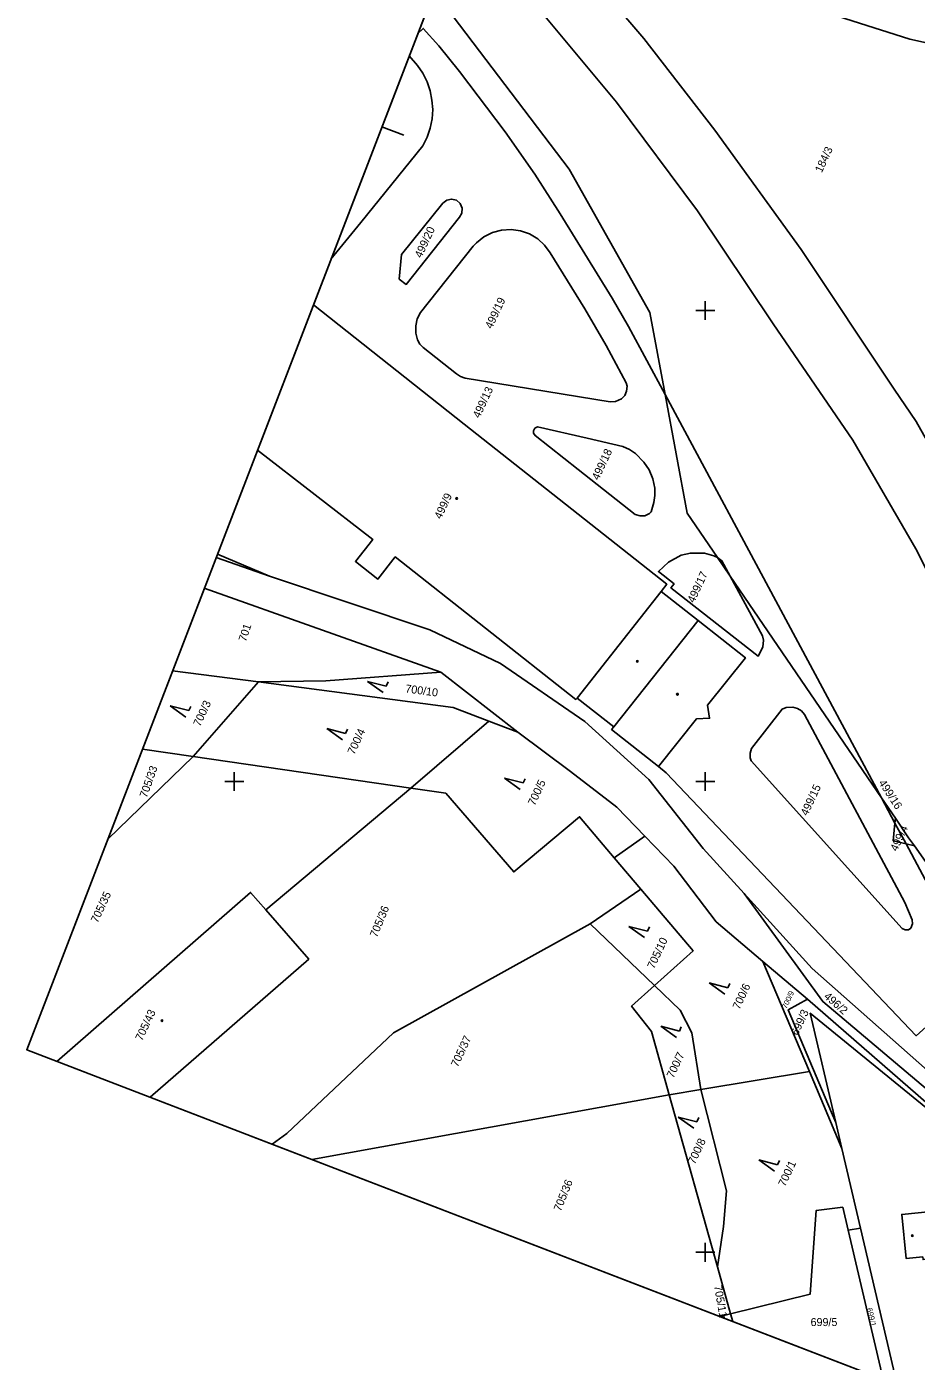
# Model space of a CAD drawing. Extents: x -755344 to -754413, y -1162670 to -1161477.
# Drawn here: x -755344.1 to -755155.2, y -1162523.1 to -1162239.7 of the extents above; entities that cross this region are included whole.
import ezdxf

# ---------------------------------------------------------------- set-up
doc = ezdxf.new("R2010")
doc.units = 0
for name, color, linetype in [('Formát', 7, 'Continuous'), ('Síť', 7, 'Continuous'), ('Vrstva 55', 7, 'Continuous'), ('Vrstva 56', 7, 'Continuous'), ('Vrstva 57', 7, 'Continuous'), ('Vrstva 58', 7, 'Continuous'), ('Vrstva 59', 7, 'Continuous')]:
    doc.layers.add(name, color=color, linetype=linetype)

msp = doc.modelspace()

# ---------------------------------------------------------------- linework, layer by layer
at = {"layer": 'Formát'}
for p, q in [((-755042.37, -1161673.02), (-755344.08, -1162456.97)), ((-755042.37, -1161673.02), (-755344.08, -1162456.97)), ((-755268.65, -1162260.99), (-755263.98, -1162262.78)), ((-755344.08, -1162456.97), (-754789.71, -1162670.32))]:
    msp.add_line(p, q, dxfattribs=at)
msp.add_lwpolyline([(-754488.01, -1161886.37), (-754789.71, -1162670.32), (-755344.08, -1162456.97), (-755042.37, -1161673.02)], close=True, dxfattribs=at)
for points in [[(-755344.08, -1162456.97), (-754789.71, -1162670.32), (-754488.01, -1161886.37), (-755042.37, -1161673.02)], [(-755344.08, -1162456.97), (-754789.71, -1162670.32), (-754488.01, -1161886.37), (-755042.37, -1161673.02)], [(-754789.71, -1162670.32), (-754488.01, -1161886.37), (-755042.37, -1161673.02), (-755344.08, -1162456.97)]]:
    msp.add_lwpolyline(points, dxfattribs=at)
at = {"layer": 'Síť'}
for points in [[(-755198, -1162300), (-755200, -1162300), (-755202, -1162300)], [(-755200, -1162298), (-755200, -1162300), (-755200, -1162302)], [(-755300, -1162398), (-755300, -1162400), (-755300, -1162402)], [(-755200, -1162398), (-755200, -1162400), (-755200, -1162402)], [(-755298, -1162400), (-755300, -1162400), (-755302, -1162400)], [(-755198, -1162400), (-755200, -1162400), (-755202, -1162400)], [(-755200, -1162498), (-755200, -1162500), (-755200, -1162502)], [(-755198, -1162500), (-755200, -1162500), (-755202, -1162500)]]:
    msp.add_lwpolyline(points, dxfattribs=at)
at = {"layer": 'Vrstva 55'}
for p, q in [((-755197.4, -1162352.43), (-755194.7, -1162356.4)), ((-755194.7, -1162356.4), (-755162.59, -1162403.5)), ((-755256.17, -1162376.79), (-755306.36, -1162358.97)), ((-755256.17, -1162376.79), (-755306.36, -1162358.97)), ((-755256.17, -1162376.79), (-755280.56, -1162378.65)), ((-755239.79, -1162389.54), (-755256.17, -1162376.79)), ((-755239.79, -1162389.54), (-755256.17, -1162376.79)), ((-755308.72, -1162394.69), (-755294.89, -1162378.88)), ((-755280.56, -1162378.65), (-755294.89, -1162378.88)), ((-755262.5, -1162401.42), (-755245.93, -1162387.2)), ((-755239.79, -1162389.54), (-755245.93, -1162387.2)), ((-755228.6, -1162397.87), (-755239.79, -1162389.54)), ((-755228.6, -1162397.87), (-755239.79, -1162389.54)), ((-755319.5, -1162393.12), (-755308.72, -1162394.69)), ((-755326.86, -1162412.25), (-755308.72, -1162394.69)), ((-755308.72, -1162394.69), (-755262.5, -1162401.42)), ((-755293.31, -1162427.26), (-755262.5, -1162401.42)), ((-755262.5, -1162401.42), (-755255.05, -1162402.51)), ((-755162.59, -1162403.5), (-755159.64, -1162407.83)), ((-755159.74, -1162408.83), (-755162.59, -1162403.5)), ((-755159.64, -1162407.83), (-755159.74, -1162408.83)), ((-755219.35, -1162416.19), (-755212.85, -1162411.61)), ((-755157.36, -1162413.27), (-755155.59, -1162413.71)), ((-755219.35, -1162416.19), (-755213.66, -1162422.91)), ((-755213.66, -1162422.91), (-755224.46, -1162430.27)), ((-755224.46, -1162430.27), (-755210.79, -1162443.34)), ((-755178.31, -1162446.22), (-755187.75, -1162438.21)), ((-755177.87, -1162461.62), (-755187.75, -1162438.21)), ((-755178.31, -1162446.22), (-755187.75, -1162438.21)), ((-755136.42, -1162482.75), (-755178.31, -1162446.22)), ((-755136.42, -1162482.75), (-755178.31, -1162446.22)), ((-755211.4, -1162453.1), (-755207.64, -1162466.53)), ((-755177.87, -1162461.62), (-755200.95, -1162465.43)), ((-755170.99, -1162477.93), (-755177.87, -1162461.62)), ((-755207.64, -1162466.53), (-755283.5, -1162480.29)), ((-755207.64, -1162466.53), (-755200.95, -1162465.43)), ((-755207.64, -1162466.53), (-755197.41, -1162503.06)), ((-755172.28, -1162472.41), (-755170.99, -1162477.93)), ((-755170.99, -1162477.93), (-755167.04, -1162494.84)), ((-755169.63, -1162495.32), (-755170.76, -1162490.41)), ((-755167.04, -1162494.84), (-755169.63, -1162495.32)), ((-755169.63, -1162495.32), (-755162.24, -1162526.95)), ((-755197.41, -1162503.06), (-755194.62, -1162513.04)), ((-755196.07, -1162513.44), (-755196.82, -1162513.65)), ((-755194.62, -1162513.04), (-755196.07, -1162513.44)), ((-755194.16, -1162514.67), (-755194.62, -1162513.04))]:
    msp.add_line(p, q, dxfattribs=at)
for points in [[(-755251.78, -1162217.14), (-755236.92, -1162234.12), (-755218.86, -1162255.78), (-755201.65, -1162278.82), (-755185.6, -1162302.84), (-755168.69, -1162327.53), (-755155.26, -1162350.62), (-755154.66, -1162351.82), (-755141.68, -1162377.77), (-755128.84, -1162403.34)], [(-755224.59, -1162220.51), (-755227.6, -1162225.16), (-755213.03, -1162242.21), (-755197.95, -1162261.69), (-755179.66, -1162287.01), (-755159.89, -1162316.68), (-755155.21, -1162323.55), (-755152.98, -1162327.62)], [(-755140.31, -1162246.01), (-755156.59, -1162242.36), (-755179.53, -1162235.08), (-755202.91, -1162226.05)], [(-755257.56, -1162232.16), (-755228.92, -1162270), (-755211.8, -1162300.42), (-755208.54, -1162317.82)], [(-755261.01, -1162241.13), (-755259.86, -1162240.09), (-755256.55, -1162243.81), (-755252.15, -1162249.27), (-755242.47, -1162262.02), (-755236.16, -1162271.02), (-755230.79, -1162279.46), (-755219.8, -1162297.35), (-755216.28, -1162303.42), (-755208.54, -1162317.82)], [(-755279.48, -1162289.12), (-755273.15, -1162281.3), (-755259.96, -1162264.99), (-755259.05, -1162263.18), (-755258.42, -1162261.28), (-755258.01, -1162259.3), (-755257.86, -1162257.3), (-755258.04, -1162255.29), (-755258.42, -1162253.32), (-755259.06, -1162251.4), (-755259.94, -1162249.61), (-755261.07, -1162247.95), (-755262.85, -1162245.91)], [(-755264.53, -1162288.11), (-755255.71, -1162277.19), (-755254.89, -1162276.55), (-755253.87, -1162276.34), (-755252.85, -1162276.59), (-755252.05, -1162277.27), (-755251.62, -1162278.23), (-755251.7, -1162279.29), (-755252.21, -1162280.19), (-755263.5, -1162294.45), (-755265.01, -1162293.32), (-755264.53, -1162288.11)], [(-755249.26, -1162286.35), (-755248.56, -1162285.61), (-755246.99, -1162284.35), (-755245.19, -1162283.44), (-755243.24, -1162282.9), (-755241.22, -1162282.77), (-755239.23, -1162283.04), (-755237.32, -1162283.7), (-755235.58, -1162284.76), (-755234.1, -1162286.1), (-755232.92, -1162287.74), (-755225.57, -1162299.65), (-755221.06, -1162307.45), (-755216.79, -1162315.38), (-755216.6, -1162316.07), (-755216.69, -1162317.09), (-755217.09, -1162318.02), (-755217.77, -1162318.78), (-755219.05, -1162319.34), (-755220.22, -1162319.37), (-755250.99, -1162314.33), (-755251.97, -1162314.01), (-755252.8, -1162313.43), (-755259.87, -1162307.84), (-755260.58, -1162307.15), (-755261.1, -1162306.25), (-755261.47, -1162304.77), (-755261.48, -1162303.26), (-755261.16, -1162301.78), (-755260.47, -1162300.43), (-755249.26, -1162286.35)], [(-755209.95, -1162396.8), (-755201.89, -1162386.73), (-755199.09, -1162386.57), (-755199.54, -1162383.8), (-755191.47, -1162373.73), (-755201.54, -1162365.82), (-755209.34, -1162359.63), (-755208.16, -1162358.13), (-755251.18, -1162324.13), (-755283.21, -1162298.82)], [(-755208.54, -1162317.82), (-755203.83, -1162343), (-755197.4, -1162352.43)], [(-755235.64, -1162324.73), (-755225.07, -1162327.13), (-755217.5, -1162328.85), (-755216.09, -1162329.51), (-755214.81, -1162330.37), (-755213.06, -1162332.17), (-755211.93, -1162333.85), (-755211.16, -1162335.75), (-755210.72, -1162337.72), (-755210.71, -1162339.28), (-755210.94, -1162340.77), (-755211.5, -1162342.72), (-755211.86, -1162343.11), (-755212.81, -1162343.61), (-755213.83, -1162343.62), (-755214.89, -1162343.31), (-755226.97, -1162333.77), (-755236.12, -1162326.55), (-755236.44, -1162326.06), (-755236.45, -1162325.52), (-755236.16, -1162325.01), (-755235.64, -1162324.73)], [(-755209.95, -1162396.8), (-755219.88, -1162388.97), (-755219.41, -1162388.42), (-755227.22, -1162382.29), (-755227.45, -1162382.59), (-755265.84, -1162352.32), (-755269.5, -1162357.01), (-755274.29, -1162353.28), (-755270.6, -1162348.62), (-755295.07, -1162329.63)], [(-755292.52, -1162356.43), (-755303.85, -1162352.45)], [(-755303.57, -1162351.72), (-755292.52, -1162356.43)], [(-755194.7, -1162356.4), (-755187.86, -1162369.11), (-755187.6, -1162370.02), (-755187.8, -1162371.5), (-755188.78, -1162373.43), (-755207.28, -1162358.88), (-755206.63, -1162358.07), (-755209.93, -1162355.45), (-755207.82, -1162353.4), (-755205.14, -1162351.97), (-755203.16, -1162351.5), (-755200.13, -1162351.55), (-755198.17, -1162352.07), (-755197.4, -1162352.43)], [(-755292.52, -1162356.43), (-755258.5, -1162367.8), (-755243.5, -1162374.93), (-755225.6, -1162387.24), (-755212.01, -1162399.57), (-755200.43, -1162414.21), (-755191.72, -1162423.82)], [(-755294.89, -1162378.88), (-755313.1, -1162376.49)], [(-755245.93, -1162387.2), (-755253.53, -1162384.31), (-755294.89, -1162378.88)], [(-755190.23, -1162395.62), (-755190.43, -1162394.96), (-755190.46, -1162393.97), (-755190.17, -1162393.03), (-755183.69, -1162384.68), (-755182.85, -1162384.3), (-755181.4, -1162384.23), (-755180.44, -1162384.49), (-755179.57, -1162384.99), (-755178.91, -1162385.78), (-755157.62, -1162425.68), (-755156.05, -1162429.38), (-755156.03, -1162430.21), (-755156.34, -1162431.15), (-755156.88, -1162431.52), (-755157.56, -1162431.53), (-755158.19, -1162431.25), (-755190.23, -1162395.62)], [(-755212.85, -1162411.61), (-755218.77, -1162405.46), (-755228.6, -1162397.87)], [(-755212.85, -1162411.61), (-755218.77, -1162405.46), (-755228.6, -1162397.87)], [(-755147.93, -1162465.72), (-755147.53, -1162465.77), (-755146.63, -1162465.33), (-755146.01, -1162464.59), (-755145.78, -1162463.97), (-755145.86, -1162463.15), (-755150.88, -1162450.09), (-755151.6, -1162450.76), (-755155.2, -1162454), (-755208.3, -1162398.17), (-755209.95, -1162396.8)], [(-755255.05, -1162402.51), (-755240.65, -1162419.2), (-755226.69, -1162407.51), (-755219.35, -1162416.19)], [(-755159.64, -1162407.83), (-755156.82, -1162411.96), (-755155.59, -1162413.71)], [(-755159.74, -1162408.83), (-755160.13, -1162412.59), (-755157.36, -1162413.27)], [(-755187.75, -1162438.21), (-755197.66, -1162429.8), (-755206.7, -1162418), (-755212.85, -1162411.61)], [(-755187.75, -1162438.21), (-755197.66, -1162429.8), (-755206.7, -1162418), (-755212.85, -1162411.61)], [(-755136.97, -1162449.09), (-755140.07, -1162450.08), (-755142.03, -1162450.09), (-755143.92, -1162449.51), (-755145.15, -1162448.68), (-755145.88, -1162447.38), (-755146.21, -1162446.45), (-755149.93, -1162428.84), (-755150.43, -1162426.9), (-755151.56, -1162424.12), (-755157.36, -1162413.27)], [(-755155.59, -1162413.71), (-755145.43, -1162428.12), (-755137.03, -1162445.6)], [(-755337.66, -1162459.44), (-755296.53, -1162423.57), (-755293.31, -1162427.26)], [(-755210.79, -1162443.34), (-755202.59, -1162436), (-755213.66, -1162422.91)], [(-755191.72, -1162423.82), (-755177.29, -1162439.75), (-755147.93, -1162465.72)], [(-755136.49, -1162478.06), (-755139.64, -1162476.61), (-755175.06, -1162446.75), (-755191.72, -1162423.82)], [(-755293.31, -1162427.26), (-755284.2, -1162437.71), (-755317.87, -1162467.06)], [(-755291.95, -1162477.03), (-755288.84, -1162474.8), (-755266.17, -1162453.41), (-755224.46, -1162430.27)], [(-755210.79, -1162443.34), (-755215.65, -1162447.7), (-755211.4, -1162453.1)], [(-755210.79, -1162443.34), (-755205.32, -1162448.57), (-755202.86, -1162453.37), (-755200.95, -1162465.43)], [(-755178.31, -1162446.22), (-755182.38, -1162448.48), (-755173.18, -1162470.28), (-755172.28, -1162472.41)], [(-755172.28, -1162472.41), (-755177.72, -1162449.23), (-755145.9, -1162475.22), (-755135.89, -1162483.24)], [(-755200.95, -1162465.43), (-755195.47, -1162486.94), (-755196.12, -1162494.51), (-755197.41, -1162503.06)], [(-755135.28, -1162489.58), (-755135.65, -1162485.61), (-755141.54, -1162486.3), (-755146.99, -1162486.73), (-755146.57, -1162490.74), (-755154.79, -1162491.58), (-755158.29, -1162491.94), (-755157.33, -1162501.33), (-755153.82, -1162500.97), (-755153.76, -1162501.54), (-755134.18, -1162499.57), (-755134.2, -1162499.29), (-755135.1, -1162489.56), (-755135.28, -1162489.58)], [(-755170.76, -1162490.41), (-755176.47, -1162491.13), (-755177.73, -1162508.9), (-755194.62, -1162513.04)], [(-755159.22, -1162528.11), (-755167.04, -1162494.84)], [(-755196.07, -1162513.44), (-755196.02, -1162513.95)]]:
    msp.add_lwpolyline(points, dxfattribs=at)
at = {"layer": 'Vrstva 56'}
for p, q in [((-755209.34, -1162359.63), (-755227.22, -1162382.29)), ((-755219.41, -1162388.42), (-755201.54, -1162365.82)), ((-755159.74, -1162408.83), (-755157.36, -1162413.27))]:
    msp.add_line(p, q, dxfattribs=at)
for points in [[(-755208.54, -1162317.82), (-755182.37, -1162366.53), (-755162.59, -1162403.5)], [(-755197.4, -1162352.43), (-755196.45, -1162353.14), (-755194.7, -1162356.4)]]:
    msp.add_lwpolyline(points, dxfattribs=at)
at = {"layer": 'Vrstva 58'}
for p, q in [((-755267.76, -1162379.78), (-755271.71, -1162378.77)), ((-755271.71, -1162378.77), (-755268.4, -1162381.14)), ((-755267.76, -1162379.78), (-755267.34, -1162378.88)), ((-755309.64, -1162384.96), (-755313.58, -1162383.95)), ((-755313.58, -1162383.95), (-755310.27, -1162386.32)), ((-755309.64, -1162384.96), (-755309.22, -1162384.06)), ((-755276.41, -1162389.8), (-755280.36, -1162388.79)), ((-755280.36, -1162388.79), (-755277.05, -1162391.16)), ((-755276.41, -1162389.8), (-755275.99, -1162388.9)), ((-755238.65, -1162400.32), (-755242.6, -1162399.31)), ((-755242.6, -1162399.31), (-755239.29, -1162401.68)), ((-755238.65, -1162400.32), (-755238.23, -1162399.42)), ((-755212.29, -1162431.79), (-755216.24, -1162430.78)), ((-755216.24, -1162430.78), (-755212.93, -1162433.15)), ((-755212.29, -1162431.79), (-755211.87, -1162430.89)), ((-755195.23, -1162443.8), (-755199.18, -1162442.79)), ((-755199.18, -1162442.79), (-755195.87, -1162445.16)), ((-755195.23, -1162443.8), (-755194.81, -1162442.9)), ((-755205.5, -1162453.01), (-755209.45, -1162452)), ((-755209.45, -1162452), (-755206.14, -1162454.37)), ((-755205.5, -1162453.01), (-755205.08, -1162452.11)), ((-755201.8, -1162472.29), (-755205.75, -1162471.28)), ((-755205.75, -1162471.28), (-755202.44, -1162473.65)), ((-755201.8, -1162472.29), (-755201.38, -1162471.39)), ((-755184.66, -1162481.39), (-755188.61, -1162480.38)), ((-755188.61, -1162480.38), (-755185.3, -1162482.75)), ((-755184.66, -1162481.39), (-755184.24, -1162480.49))]:
    msp.add_line(p, q, dxfattribs=at)
at = {"layer": 'Vrstva 59'}
for centre in [(-755252.79, -1162339.91), (-755214.42, -1162374.51), (-755205.91, -1162381.48), (-755315.36, -1162450.82), (-755156.02, -1162496.46)]:
    msp.add_circle(centre, 0.175, dxfattribs=at)

# ---------------------------------------------------------------- texts
at = {"layer": 'Vrstva 57'}
for s, height, rotation, p in [('184/3', 1.7, 65, (-755175.27, -1162270.86)), ('499/20', 1.7, 65, (-755260.27, -1162288.97)), ('499/19', 1.7, 65, (-755245.31, -1162304.02)), ('499/13', 1.7, 65, (-755247.93, -1162322.99)), ('499/18', 1.7, 65, (-755222.65, -1162336.15)), ('499/9', 1.7, 65, (-755256.1, -1162344.43)), ('499/17', 1.7, 65, (-755202.36, -1162362.22)), ('701', 1.7, 71.5779, (-755297.54, -1162370.44)), ('700/10', 1.7, 352.4757, (-755263.76, -1162381.08)), ('700/3', 1.7, 65, (-755307.27, -1162388.47)), ('700/4', 1.7, 65, (-755274.52, -1162394.45)), ('705/33', 1.7, 70.511, (-755318.57, -1162403.6)), ('700/5', 1.7, 65, (-755236.21, -1162405.29)), ('499/15', 1.7, 65, (-755178.31, -1162407.43)), ('499/16', 1.7, 303.3494, (-755163.29, -1162400.3)), ('499/4', 1.7, 65, (-755159.3, -1162414.99)), ('705/35', 1.7, 65, (-755329.02, -1162430.19)), ('705/36', 1.7, 67.4349, (-755269.73, -1162433.25)), ('705/10', 1.7, 65, (-755210.87, -1162439.94)), ('700/6', 1.7, 65, (-755192.75, -1162448.56)), ('700/9', 1.139, 65, (-755182.75, -1162448.38)), ('496/2', 1.7, 318.8413, (-755174.94, -1162445.87)), ('705/43', 1.7, 65, (-755319.57, -1162455.24)), ('699/3', 1.7, 65, (-755180.37, -1162454.09)), ('705/37', 1.7, 65, (-755252.55, -1162460.8)), ('700/7', 1.7, 65, (-755206.76, -1162463.15)), ('700/8', 1.7, 65, (-755202.23, -1162481.44)), ('700/1', 1.7, 65, (-755183.05, -1162486.18)), ('705/36', 1.7, 68.074, (-755230.69, -1162491.43)), ('705/11', 1.7, 280, (-755198.16, -1162507.15)), ('699/1', 1.2, 284, (-755165.77, -1162511.96))]:
    msp.add_text(s, height=height, rotation=rotation, dxfattribs=at).set_placement(p)
msp.add_text('699/5', height=1.7, dxfattribs=at).set_placement((-755177.64, -1162515.66))

doc.saveas('drawing.dxf')
